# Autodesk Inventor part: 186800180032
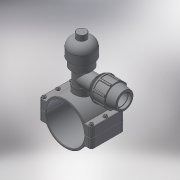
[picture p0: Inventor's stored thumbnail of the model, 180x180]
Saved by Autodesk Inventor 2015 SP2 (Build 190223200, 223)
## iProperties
Created: 2017-05
Part Number: 186800180032
Material: Generic
Description: PLASSON MECHANICAL TAPPING VALVE 180-32
Document SubType Name: Modeling
Designer: KIM
Density: 1 g/cm^3
Appearance: Default
Author: KIM
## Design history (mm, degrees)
derived "18680.ipt"
feature "Solid1::18680.ipt"
feature "Solid2::18680.ipt"
tag "TaggingFeature1"
body "Solid1"
other parameters: "d0" = 198, "d1" = 245, "d4" = 154, "d5" = 0, "d6" = 12.25, "d7" = 245, "d8" = 0.1, "d10" = 0, "d11" = 1.8, "d14" = 50.6376, "d20" = 1.8, "d23" = 1.8, "d36" = 15, "d37" = 12, "d38" = 98, "d39" = 0, "d40" = 3, "d41" = 5, "d42" = 0, "d44" = 3, "d45" = 0, "d46" = 1.8, "d51" = 127, "d52" = 38.952, "d53" = 25, "d54" = 0, "d55" = 32, "d57" = 0, "d58" = 194.4, "d60" = 0, "d62" = 15, "d63" = 12, "d67" = 32, "d68" = 11.25, "d69" = 27, "d70" = 64, "d71" = 48, "d72" = 1.92857, "d73" = 51.2, "d74" = 120 deg, "d75" = 48, "d76" = 10 deg, "d77" = 57.6, "d78" = 40.5, "d79" = 67, "d80" = 25.6, "d81" = 135, "d82" = 6.7, "d87" = 19.28571, "d90" = 59.52, "d91" = 35 deg, "d92" = 17.5 deg, "d94" = 0, "d96" = 360 deg, "d98" = 0.64, "d99" = 73.7, "d100" = 38.4, "d101" = 135 deg, "d102" = 1.28, "d105" = 3.2, "d106" = 0, "d107" = 0.1, "d109" = 50.6376, "d112" = 34.85714, "d113" = 4.5, "d116" = 0, "d121" = 46.7424, "d122" = 77.904, "d123" = 66.2184, "d124" = 45 deg, "d125" = 219.6, "d126" = 244, "d127" = 146.4, "d128" = 1, "B_" = 32, "G_" = 38.952, "A_" = 127, "L_" = 245, "L_1" = 154, "l_2" = 25, "d_1" = 32, "E_" = 64, "l_" = 67, "H_" = 135, "H_2" = 244
